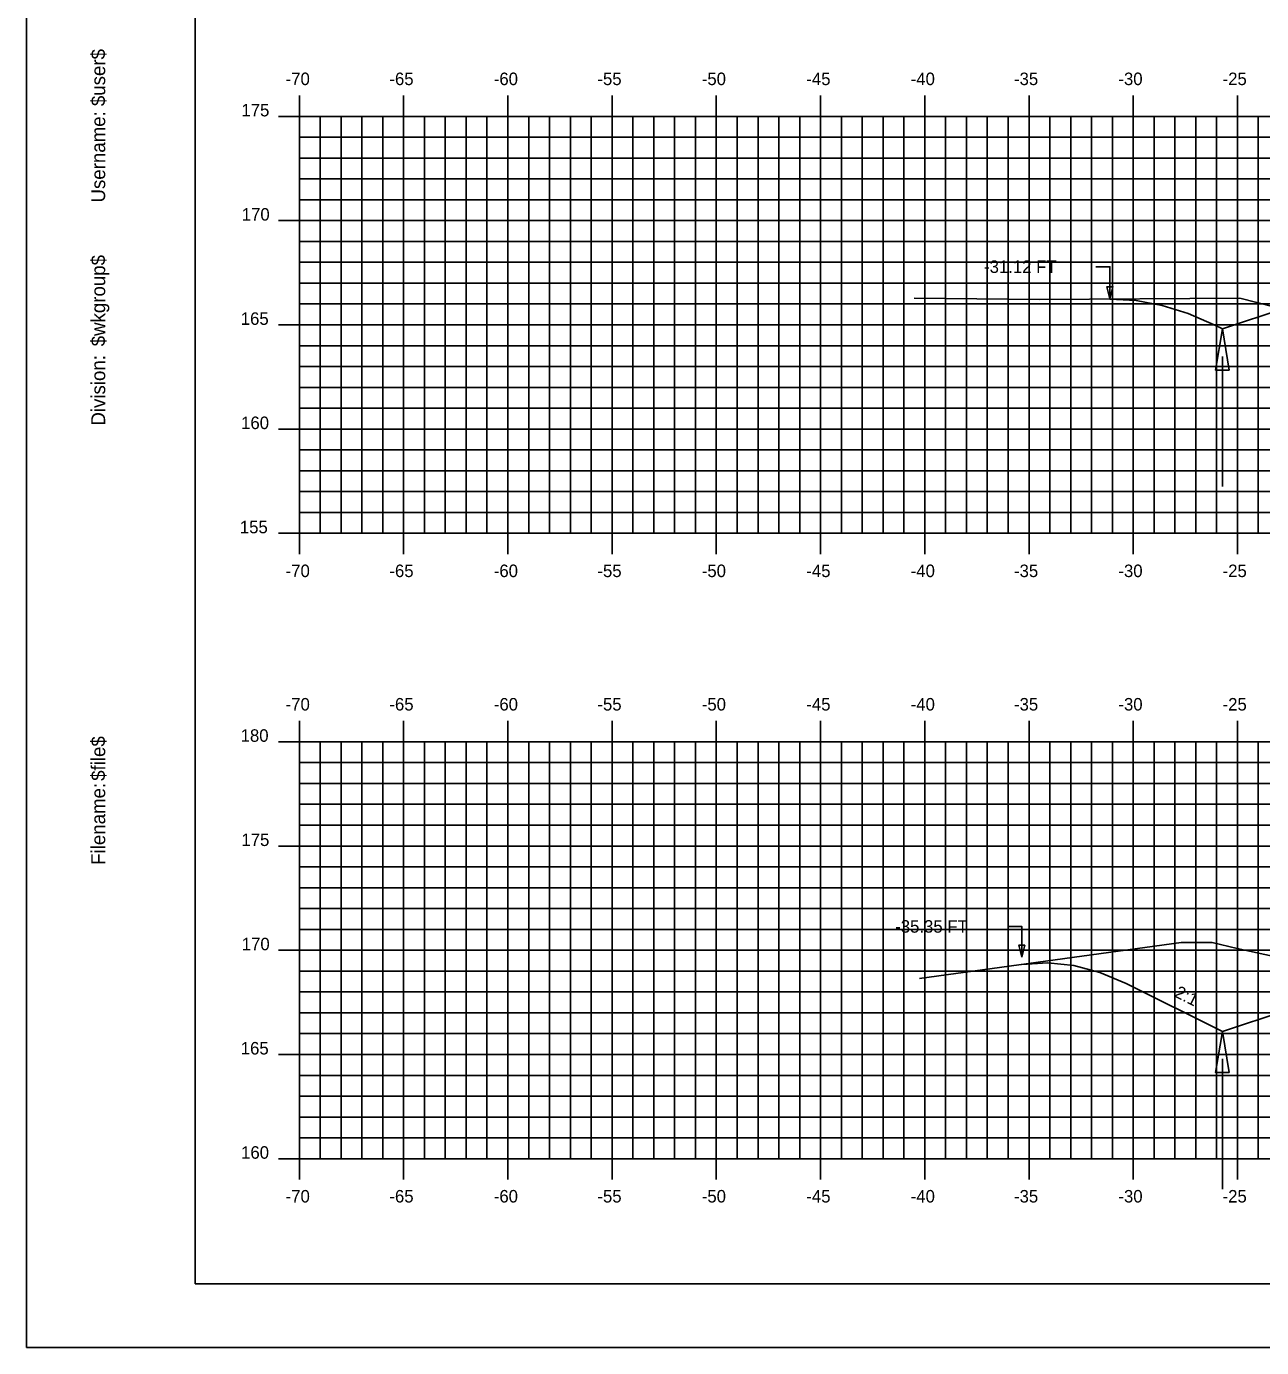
# Model space of a CAD drawing. Extents: x 1140759 to 1140929, y 608981 to 609091.
# Drawn here: x 1140758.9 to 1140818.2, y 608981.3 to 609044.6 of the extents above; entities that cross this region are included whole.
import ezdxf

# ---------------------------------------------------------------- set-up
doc = ezdxf.new("R2010")
doc.units = 0
for name, color, linetype in [('ANNOTATION', 7, 'Continuous'), ('BORDER', 7, 'Continuous'), ('D_Drainage_Ditch_Line', 7, 'Continuous'), ('D_Roadway_SlopeLines', 7, 'Continuous'), ('D_Text_Standard', 7, 'Continuous'), ('H_V ANNOTATION', 7, 'Continuous'), ('MAJOR', 7, 'Continuous'), ('MINOR', 7, 'Continuous'), ('PLOT BOUNDARY', 7, 'Continuous'), ('S_Roadway_Centerline', 7, 'Continuous')]:
    doc.layers.add(name, color=color, linetype=linetype)

msp = doc.modelspace()

# ---------------------------------------------------------------- linework, layer by layer
for points in [[(1140810.883, 609031.567), (1140812.133, 609031.496), (1140813.383, 609031.267), (1140814.633, 609030.879), (1140815.883, 609030.333), (1140816.276, 609030.136), (1140819.276, 609031.136), (1140827, 609033.711), (1140827.001, 609033.711), (1140831.001, 609033.871), (1140842.001, 609034.091), (1140853.001, 609033.871), (1140859.098, 609033.627), (1140866.688, 609031.097), (1140869.688, 609030.097), (1140875.149, 609032.828), (1140876.399, 609033.379), (1140877.649, 609033.781), (1140878.899, 609034.035), (1140880.149, 609034.141)], [(1140806.654, 608999.652), (1140807.904, 608999.725), (1140809.154, 608999.598), (1140810.404, 608999.272), (1140811.654, 608998.747), (1140816.276, 608996.435), (1140819.276, 608997.435), (1140827, 609000.01), (1140827.001, 609000.01), (1140831.001, 609000.17), (1140842.001, 609000.39), (1140853.001, 609000.17), (1140857.001, 609000.01), (1140864.725, 608997.435), (1140867.725, 608996.435), (1140882.606, 609003.876), (1140883.856, 609004.435), (1140885.106, 609004.861), (1140886.356, 609005.154), (1140887.606, 609005.314)]]:
    msp.add_lwpolyline(points)
at = {"layer": 'BORDER'}
msp.add_lwpolyline([(1140767.001, 608984.335), (1140927.001, 608984.335), (1140927.001, 609089.335), (1140767.001, 609089.335)], close=True, dxfattribs=at)
at = {"layer": 'D_Drainage_Ditch_Line'}
for p, q in [((1140816.277, 609028.824), (1140816.276, 609022.58)), ((1140816.277, 608995.123), (1140816.276, 608988.879))]:
    msp.add_line(p, q, dxfattribs=at)
for points in [[(1140816.605, 609028.168), (1140815.948, 609028.168), (1140816.276, 609030.136)], [(1140816.605, 608994.467), (1140815.948, 608994.467), (1140816.276, 608996.435)]]:
    msp.add_lwpolyline(points, close=True, dxfattribs=at)
at = {"layer": 'D_Roadway_SlopeLines'}
for points in [[(1140816.276, 609030.136), (1140815.883, 609030.333), (1140814.633, 609030.879), (1140813.383, 609031.267), (1140812.133, 609031.496), (1140810.883, 609031.567)], [(1140819.276, 609031.136), (1140816.276, 609030.136)], [(1140816.276, 608996.435), (1140811.654, 608998.747), (1140810.404, 608999.272), (1140809.154, 608999.598), (1140807.904, 608999.725), (1140806.654, 608999.652)], [(1140819.276, 608997.435), (1140816.276, 608996.435)]]:
    msp.add_lwpolyline(points, dxfattribs=at)
at = {"layer": 'D_Text_Standard'}
for points in [[(1140810.883, 609031.583), (1140810.884, 609033.125), (1140810.204, 609033.125)], [(1140806.654, 608999.997), (1140806.654, 609001.478), (1140805.974, 609001.478)]]:
    msp.add_lwpolyline(points, dxfattribs=at)
for points in [[(1140810.883, 609031.583), (1140810.737, 609032.165), (1140811.029, 609032.165)], [(1140806.654, 608999.997), (1140806.508, 609000.579), (1140806.799, 609000.579)]]:
    msp.add_lwpolyline(points, close=True, dxfattribs=at)
at = {"layer": 'MAJOR'}
for p, q in [((1140772.001, 609041.337), (1140772.001, 609040.335)), ((1140777.001, 609041.337), (1140777.001, 609040.335)), ((1140782.001, 609041.337), (1140782.001, 609040.335)), ((1140787.001, 609041.337), (1140787.001, 609040.335)), ((1140792.001, 609041.337), (1140792.001, 609040.335)), ((1140797.001, 609041.337), (1140797.001, 609040.335)), ((1140802.001, 609041.337), (1140802.001, 609040.335)), ((1140807.001, 609041.337), (1140807.001, 609040.335)), ((1140812.001, 609041.337), (1140812.001, 609040.335)), ((1140817.001, 609041.337), (1140817.001, 609040.335)), ((1140770.999, 609040.335), (1140772.001, 609040.335)), ((1140772.001, 609040.335), (1140912.001, 609040.335)), ((1140772.001, 609020.335), (1140772.001, 609040.335)), ((1140772.001, 609020.335), (1140772.001, 609040.335)), ((1140772.001, 609040.335), (1140912.001, 609040.335)), ((1140777.001, 609020.335), (1140777.001, 609040.335)), ((1140782.001, 609020.335), (1140782.001, 609040.335)), ((1140787.001, 609020.335), (1140787.001, 609040.335)), ((1140792.001, 609020.335), (1140792.001, 609040.335)), ((1140797.001, 609020.335), (1140797.001, 609040.335)), ((1140802.001, 609020.335), (1140802.001, 609040.335)), ((1140807.001, 609020.335), (1140807.001, 609040.335)), ((1140812.001, 609020.335), (1140812.001, 609040.335)), ((1140817.001, 609020.335), (1140817.001, 609040.335)), ((1140770.999, 609035.335), (1140772.001, 609035.335)), ((1140772.001, 609035.335), (1140912.001, 609035.335)), ((1140770.999, 609030.335), (1140772.001, 609030.335)), ((1140772.001, 609030.335), (1140912.001, 609030.335)), ((1140770.999, 609025.335), (1140772.001, 609025.335)), ((1140772.001, 609025.335), (1140912.001, 609025.335)), ((1140770.999, 609020.335), (1140772.001, 609020.335)), ((1140772.001, 609020.335), (1140912.001, 609020.335)), ((1140772.001, 609020.335), (1140912.001, 609020.335)), ((1140772.001, 609019.333), (1140772.001, 609020.335)), ((1140777.001, 609019.333), (1140777.001, 609020.335)), ((1140782.001, 609019.333), (1140782.001, 609020.335)), ((1140787.001, 609019.333), (1140787.001, 609020.335)), ((1140792.001, 609019.333), (1140792.001, 609020.335)), ((1140797.001, 609019.333), (1140797.001, 609020.335)), ((1140802.001, 609019.333), (1140802.001, 609020.335)), ((1140807.001, 609019.333), (1140807.001, 609020.335)), ((1140812.001, 609019.333), (1140812.001, 609020.335)), ((1140817.001, 609019.333), (1140817.001, 609020.335)), ((1140772.001, 609011.337), (1140772.001, 609010.335)), ((1140777.001, 609011.337), (1140777.001, 609010.335)), ((1140782.001, 609011.337), (1140782.001, 609010.335)), ((1140787.001, 609011.337), (1140787.001, 609010.335)), ((1140792.001, 609011.337), (1140792.001, 609010.335)), ((1140797.001, 609011.337), (1140797.001, 609010.335)), ((1140802.001, 609011.337), (1140802.001, 609010.335)), ((1140807.001, 609011.337), (1140807.001, 609010.335)), ((1140812.001, 609011.337), (1140812.001, 609010.335)), ((1140817.001, 609011.337), (1140817.001, 609010.335)), ((1140770.999, 609010.335), (1140772.001, 609010.335)), ((1140772.001, 609010.335), (1140912.001, 609010.335)), ((1140772.001, 608990.335), (1140772.001, 609010.335)), ((1140772.001, 608990.335), (1140772.001, 609010.335)), ((1140772.001, 609010.335), (1140912.001, 609010.335)), ((1140777.001, 608990.335), (1140777.001, 609010.335)), ((1140782.001, 608990.335), (1140782.001, 609010.335)), ((1140787.001, 608990.335), (1140787.001, 609010.335)), ((1140792.001, 608990.335), (1140792.001, 609010.335)), ((1140797.001, 608990.335), (1140797.001, 609010.335)), ((1140802.001, 608990.335), (1140802.001, 609010.335)), ((1140807.001, 608990.335), (1140807.001, 609010.335)), ((1140812.001, 608990.335), (1140812.001, 609010.335)), ((1140817.001, 608990.335), (1140817.001, 609010.335)), ((1140770.999, 609005.335), (1140772.001, 609005.335)), ((1140772.001, 609005.335), (1140912.001, 609005.335)), ((1140770.999, 609000.335), (1140772.001, 609000.335)), ((1140772.001, 609000.335), (1140912.001, 609000.335)), ((1140770.999, 608995.335), (1140772.001, 608995.335)), ((1140772.001, 608995.335), (1140912.001, 608995.335)), ((1140770.999, 608990.335), (1140772.001, 608990.335)), ((1140772.001, 608990.335), (1140912.001, 608990.335)), ((1140772.001, 608990.335), (1140912.001, 608990.335)), ((1140772.001, 608989.333), (1140772.001, 608990.335)), ((1140777.001, 608989.333), (1140777.001, 608990.335)), ((1140782.001, 608989.333), (1140782.001, 608990.335)), ((1140787.001, 608989.333), (1140787.001, 608990.335)), ((1140792.001, 608989.333), (1140792.001, 608990.335)), ((1140797.001, 608989.333), (1140797.001, 608990.335)), ((1140802.001, 608989.333), (1140802.001, 608990.335)), ((1140807.001, 608989.333), (1140807.001, 608990.335)), ((1140812.001, 608989.333), (1140812.001, 608990.335)), ((1140817.001, 608989.333), (1140817.001, 608990.335))]:
    msp.add_line(p, q, dxfattribs=at)
at = {"layer": 'MINOR'}
for p, q in [((1140773.001, 609020.335), (1140773.001, 609040.335)), ((1140774.001, 609020.335), (1140774.001, 609040.335)), ((1140775.001, 609020.335), (1140775.001, 609040.335)), ((1140776.001, 609020.335), (1140776.001, 609040.335)), ((1140778.001, 609020.335), (1140778.001, 609040.335)), ((1140779.001, 609020.335), (1140779.001, 609040.335)), ((1140780.001, 609020.335), (1140780.001, 609040.335)), ((1140781.001, 609020.335), (1140781.001, 609040.335)), ((1140783.001, 609020.335), (1140783.001, 609040.335)), ((1140784.001, 609020.335), (1140784.001, 609040.335)), ((1140785.001, 609020.335), (1140785.001, 609040.335)), ((1140786.001, 609020.335), (1140786.001, 609040.335)), ((1140788.001, 609020.335), (1140788.001, 609040.335)), ((1140789.001, 609020.335), (1140789.001, 609040.335)), ((1140790.001, 609020.335), (1140790.001, 609040.335)), ((1140791.001, 609020.335), (1140791.001, 609040.335)), ((1140793.001, 609020.335), (1140793.001, 609040.335)), ((1140794.001, 609020.335), (1140794.001, 609040.335)), ((1140795.001, 609020.335), (1140795.001, 609040.335)), ((1140796.001, 609020.335), (1140796.001, 609040.335)), ((1140798.001, 609020.335), (1140798.001, 609040.335)), ((1140799.001, 609020.335), (1140799.001, 609040.335)), ((1140800.001, 609020.335), (1140800.001, 609040.335)), ((1140801.001, 609020.335), (1140801.001, 609040.335)), ((1140803.001, 609020.335), (1140803.001, 609040.335)), ((1140804.001, 609020.335), (1140804.001, 609040.335)), ((1140805.001, 609020.335), (1140805.001, 609040.335)), ((1140806.001, 609020.335), (1140806.001, 609040.335)), ((1140808.001, 609020.335), (1140808.001, 609040.335)), ((1140809.001, 609020.335), (1140809.001, 609040.335)), ((1140810.001, 609020.335), (1140810.001, 609040.335)), ((1140811.001, 609020.335), (1140811.001, 609040.335)), ((1140813.001, 609020.335), (1140813.001, 609040.335)), ((1140814.001, 609020.335), (1140814.001, 609040.335)), ((1140815.001, 609020.335), (1140815.001, 609040.335)), ((1140816.001, 609020.335), (1140816.001, 609040.335)), ((1140818.001, 609020.335), (1140818.001, 609040.335)), ((1140772.001, 609039.335), (1140912.001, 609039.335)), ((1140772.001, 609039.335), (1140773.003, 609039.335)), ((1140772.001, 609038.335), (1140912.001, 609038.335)), ((1140772.001, 609038.335), (1140773.003, 609038.335)), ((1140772.001, 609037.335), (1140912.001, 609037.335)), ((1140772.001, 609037.335), (1140773.003, 609037.335)), ((1140772.001, 609036.335), (1140912.001, 609036.335)), ((1140772.001, 609036.335), (1140773.003, 609036.335)), ((1140772.001, 609034.335), (1140912.001, 609034.335)), ((1140772.001, 609034.335), (1140773.003, 609034.335)), ((1140772.001, 609033.335), (1140912.001, 609033.335)), ((1140772.001, 609033.335), (1140773.003, 609033.335)), ((1140772.001, 609032.335), (1140912.001, 609032.335)), ((1140772.001, 609032.335), (1140773.003, 609032.335)), ((1140772.001, 609031.335), (1140912.001, 609031.335)), ((1140772.001, 609031.335), (1140773.003, 609031.335)), ((1140772.001, 609029.335), (1140912.001, 609029.335)), ((1140772.001, 609029.335), (1140773.003, 609029.335)), ((1140772.001, 609028.335), (1140912.001, 609028.335)), ((1140772.001, 609028.335), (1140773.003, 609028.335)), ((1140772.001, 609027.335), (1140912.001, 609027.335)), ((1140772.001, 609027.335), (1140773.003, 609027.335)), ((1140772.001, 609026.335), (1140912.001, 609026.335)), ((1140772.001, 609026.335), (1140773.003, 609026.335)), ((1140772.001, 609024.335), (1140912.001, 609024.335)), ((1140772.001, 609024.335), (1140773.003, 609024.335)), ((1140772.001, 609023.335), (1140912.001, 609023.335)), ((1140772.001, 609023.335), (1140773.003, 609023.335)), ((1140772.001, 609022.335), (1140912.001, 609022.335)), ((1140772.001, 609022.335), (1140773.003, 609022.335)), ((1140772.001, 609021.335), (1140912.001, 609021.335)), ((1140772.001, 609021.335), (1140773.003, 609021.335)), ((1140773.001, 608990.335), (1140773.001, 609010.335)), ((1140774.001, 608990.335), (1140774.001, 609010.335)), ((1140775.001, 608990.335), (1140775.001, 609010.335)), ((1140776.001, 608990.335), (1140776.001, 609010.335)), ((1140778.001, 608990.335), (1140778.001, 609010.335)), ((1140779.001, 608990.335), (1140779.001, 609010.335)), ((1140780.001, 608990.335), (1140780.001, 609010.335)), ((1140781.001, 608990.335), (1140781.001, 609010.335)), ((1140783.001, 608990.335), (1140783.001, 609010.335)), ((1140784.001, 608990.335), (1140784.001, 609010.335)), ((1140785.001, 608990.335), (1140785.001, 609010.335)), ((1140786.001, 608990.335), (1140786.001, 609010.335)), ((1140788.001, 608990.335), (1140788.001, 609010.335)), ((1140789.001, 608990.335), (1140789.001, 609010.335)), ((1140790.001, 608990.335), (1140790.001, 609010.335)), ((1140791.001, 608990.335), (1140791.001, 609010.335)), ((1140793.001, 608990.335), (1140793.001, 609010.335)), ((1140794.001, 608990.335), (1140794.001, 609010.335)), ((1140795.001, 608990.335), (1140795.001, 609010.335)), ((1140796.001, 608990.335), (1140796.001, 609010.335)), ((1140798.001, 608990.335), (1140798.001, 609010.335)), ((1140799.001, 608990.335), (1140799.001, 609010.335)), ((1140800.001, 608990.335), (1140800.001, 609010.335)), ((1140801.001, 608990.335), (1140801.001, 609010.335)), ((1140803.001, 608990.335), (1140803.001, 609010.335)), ((1140804.001, 608990.335), (1140804.001, 609010.335)), ((1140805.001, 608990.335), (1140805.001, 609010.335)), ((1140806.001, 608990.335), (1140806.001, 609010.335)), ((1140808.001, 608990.335), (1140808.001, 609010.335)), ((1140809.001, 608990.335), (1140809.001, 609010.335)), ((1140810.001, 608990.335), (1140810.001, 609010.335)), ((1140811.001, 608990.335), (1140811.001, 609010.335)), ((1140813.001, 608990.335), (1140813.001, 609010.335)), ((1140814.001, 608990.335), (1140814.001, 609010.335)), ((1140815.001, 608990.335), (1140815.001, 609010.335)), ((1140816.001, 608990.335), (1140816.001, 609010.335)), ((1140818.001, 608990.335), (1140818.001, 609010.335)), ((1140772.001, 609009.335), (1140912.001, 609009.335)), ((1140772.001, 609009.335), (1140773.003, 609009.335)), ((1140772.001, 609008.335), (1140912.001, 609008.335)), ((1140772.001, 609008.335), (1140773.003, 609008.335)), ((1140772.001, 609007.335), (1140912.001, 609007.335)), ((1140772.001, 609007.335), (1140773.003, 609007.335)), ((1140772.001, 609006.335), (1140912.001, 609006.335)), ((1140772.001, 609006.335), (1140773.003, 609006.335)), ((1140772.001, 609004.335), (1140912.001, 609004.335)), ((1140772.001, 609004.335), (1140773.003, 609004.335)), ((1140772.001, 609003.335), (1140912.001, 609003.335)), ((1140772.001, 609003.335), (1140773.003, 609003.335)), ((1140772.001, 609002.335), (1140912.001, 609002.335)), ((1140772.001, 609002.335), (1140773.003, 609002.335)), ((1140772.001, 609001.335), (1140912.001, 609001.335)), ((1140772.001, 609001.335), (1140773.003, 609001.335)), ((1140772.001, 608999.335), (1140912.001, 608999.335)), ((1140772.001, 608999.335), (1140773.003, 608999.335)), ((1140772.001, 608998.335), (1140912.001, 608998.335)), ((1140772.001, 608998.335), (1140773.003, 608998.335)), ((1140772.001, 608997.335), (1140912.001, 608997.335)), ((1140772.001, 608997.335), (1140773.003, 608997.335)), ((1140772.001, 608996.335), (1140912.001, 608996.335)), ((1140772.001, 608996.335), (1140773.003, 608996.335)), ((1140772.001, 608994.335), (1140912.001, 608994.335)), ((1140772.001, 608994.335), (1140773.003, 608994.335)), ((1140772.001, 608993.335), (1140912.001, 608993.335)), ((1140772.001, 608993.335), (1140773.003, 608993.335)), ((1140772.001, 608992.335), (1140912.001, 608992.335)), ((1140772.001, 608992.335), (1140773.003, 608992.335)), ((1140772.001, 608991.335), (1140912.001, 608991.335)), ((1140772.001, 608991.335), (1140773.003, 608991.335))]:
    msp.add_line(p, q, dxfattribs=at)
at = {"layer": 'PLOT BOUNDARY'}
msp.add_lwpolyline([(1140758.908, 608981.276), (1140928.908, 608981.276), (1140928.908, 609091.276), (1140758.908, 609091.276)], close=True, dxfattribs=at)
at = {"layer": 'S_Roadway_Centerline'}
for points in [[(1140801.487, 609031.61), (1140807.51, 609031.545), (1140817.109, 609031.607), (1140818.751, 609031.199), (1140823.239, 609030.006), (1140825.606, 609030.431), (1140826.984, 609030.636), (1140828.295, 609030.749), (1140830.088, 609030.938), (1140836.661, 609031.15), (1140841.085, 609031.284), (1140845.133, 609031.054), (1140851.798, 609030.843), (1140853.505, 609030.727), (1140854.754, 609030.632), (1140856.271, 609030.176), (1140858.918, 609029.531), (1140863.578, 609031.533), (1140867.623, 609033.826), (1140881.853, 609034.183), (1140886.58, 609034.308), (1140902.941, 609034.493), (1140912.001, 609034.621)], [(1140801.751, 608998.976), (1140814.306, 609000.707), (1140815.787, 609000.705), (1140816.993, 609000.418), (1140823.481, 608999.018), (1140825.828, 608999.368), (1140826.874, 608999.635), (1140827.996, 608999.704), (1140830.23, 608999.898), (1140837.667, 609000.12), (1140841.075, 609000.147), (1140848.107, 608999.748), (1140851.527, 608999.693), (1140853.662, 608999.523), (1140854.647, 608999.437), (1140857.22, 608998.676), (1140858.176, 608998.42), (1140865.509, 609002.587), (1140868.086, 609003.78), (1140874.07, 609004.299), (1140887.7, 609005.321), (1140893.531, 609005.124), (1140897.997, 609004.657), (1140912.001, 609005.073)]]:
    msp.add_lwpolyline(points, dxfattribs=at)

# ---------------------------------------------------------------- texts
at = {"layer": 'ANNOTATION'}
msp.add_text('2:1', height=0.6, rotation=333.43495, dxfattribs=at).set_placement((1140813.932, 608998.126))
at = {"layer": 'BORDER'}
for s, p in [('$user$', (1140762.686, 609040.827)), ('Username:', (1140762.686, 609036.203)), ('$wkgroup$', (1140762.686, 609029.305)), ('Division:', (1140762.686, 609025.501)), ('$file$', (1140762.686, 609008.461)), ('Filename:', (1140762.686, 609004.433))]:
    msp.add_text(s, height=0.6696, rotation=90, dxfattribs=at).set_placement(p)
at = {"layer": 'D_Text_Standard'}
for s, p in [('-31.12 FT', (1140804.845, 609032.825)), ('-35.35 FT', (1140800.583, 609001.178))]:
    msp.add_text(s, height=0.6, dxfattribs=at).set_placement(p)
at = {"layer": 'H_V ANNOTATION'}
for s, p in [('-70', (1140771.343, 609041.835)), ('-65', (1140776.319, 609041.835)), ('-60', (1140781.327, 609041.835)), ('-55', (1140786.297, 609041.835)), ('-50', (1140791.305, 609041.835)), ('-45', (1140796.319, 609041.835)), ('-40', (1140801.327, 609041.835)), ('-35', (1140806.281, 609041.835)), ('-30', (1140811.289, 609041.835)), ('-25', (1140816.287, 609041.835)), ('175', (1140769.222, 609040.335)), ('170', (1140769.238, 609035.335)), ('165', (1140769.19, 609030.335)), ('160', (1140769.206, 609025.335)), ('155', (1140769.147, 609020.335)), ('-70', (1140771.343, 609018.235)), ('-65', (1140776.319, 609018.235)), ('-60', (1140781.327, 609018.235)), ('-55', (1140786.297, 609018.235)), ('-50', (1140791.305, 609018.235)), ('-45', (1140796.319, 609018.235)), ('-40', (1140801.327, 609018.235)), ('-35', (1140806.281, 609018.235)), ('-30', (1140811.289, 609018.235)), ('-25', (1140816.287, 609018.235)), ('-70', (1140771.343, 609011.835)), ('-65', (1140776.319, 609011.835)), ('-60', (1140781.327, 609011.835)), ('-55', (1140786.297, 609011.835)), ('-50', (1140791.305, 609011.835)), ('-45', (1140796.319, 609011.835)), ('-40', (1140801.327, 609011.835)), ('-35', (1140806.281, 609011.835)), ('-30', (1140811.289, 609011.835)), ('-25', (1140816.287, 609011.835)), ('180', (1140769.184, 609010.335)), ('175', (1140769.222, 609005.335)), ('170', (1140769.238, 609000.335)), ('165', (1140769.19, 608995.335)), ('160', (1140769.206, 608990.335)), ('-70', (1140771.343, 608988.235)), ('-65', (1140776.319, 608988.235)), ('-60', (1140781.327, 608988.235)), ('-55', (1140786.297, 608988.235)), ('-50', (1140791.305, 608988.235)), ('-45', (1140796.319, 608988.235)), ('-40', (1140801.327, 608988.235)), ('-35', (1140806.281, 608988.235)), ('-30', (1140811.289, 608988.235)), ('-25', (1140816.287, 608988.235))]:
    msp.add_text(s, height=0.6, dxfattribs=at).set_placement(p)
at = {"layer": 'MAJOR'}
for p in [(1140771.997, 609020.335), (1140771.997, 608990.335)]:
    msp.add_text('-', height=0.006, dxfattribs=at).set_placement(p)

doc.saveas('drawing.dxf')
